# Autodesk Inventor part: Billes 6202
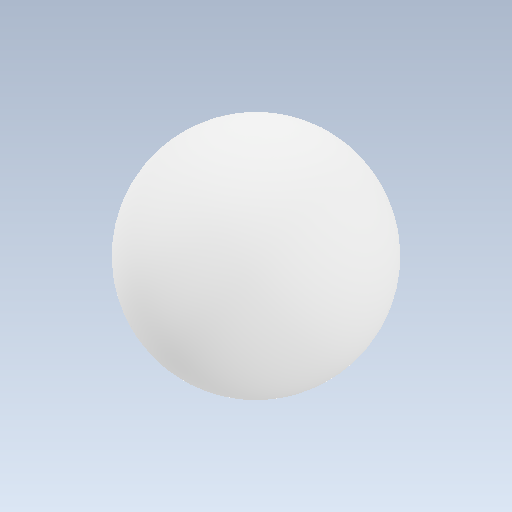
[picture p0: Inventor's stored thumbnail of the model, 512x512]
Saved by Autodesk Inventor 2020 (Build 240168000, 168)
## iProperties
Created: 2003-07
Part Number: Billes 6202
Material: Générique
Document SubType Name: Modeling
Designer: Bruno
Density: 1 g/cm^3
Appearance: Par défaut
Author: Bruno
Sending System: SolidWorks 2011
Last Author: frederic
Last Saved: 2012-02-20
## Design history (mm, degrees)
feature "Base-Révolution"
node "Solide1"
